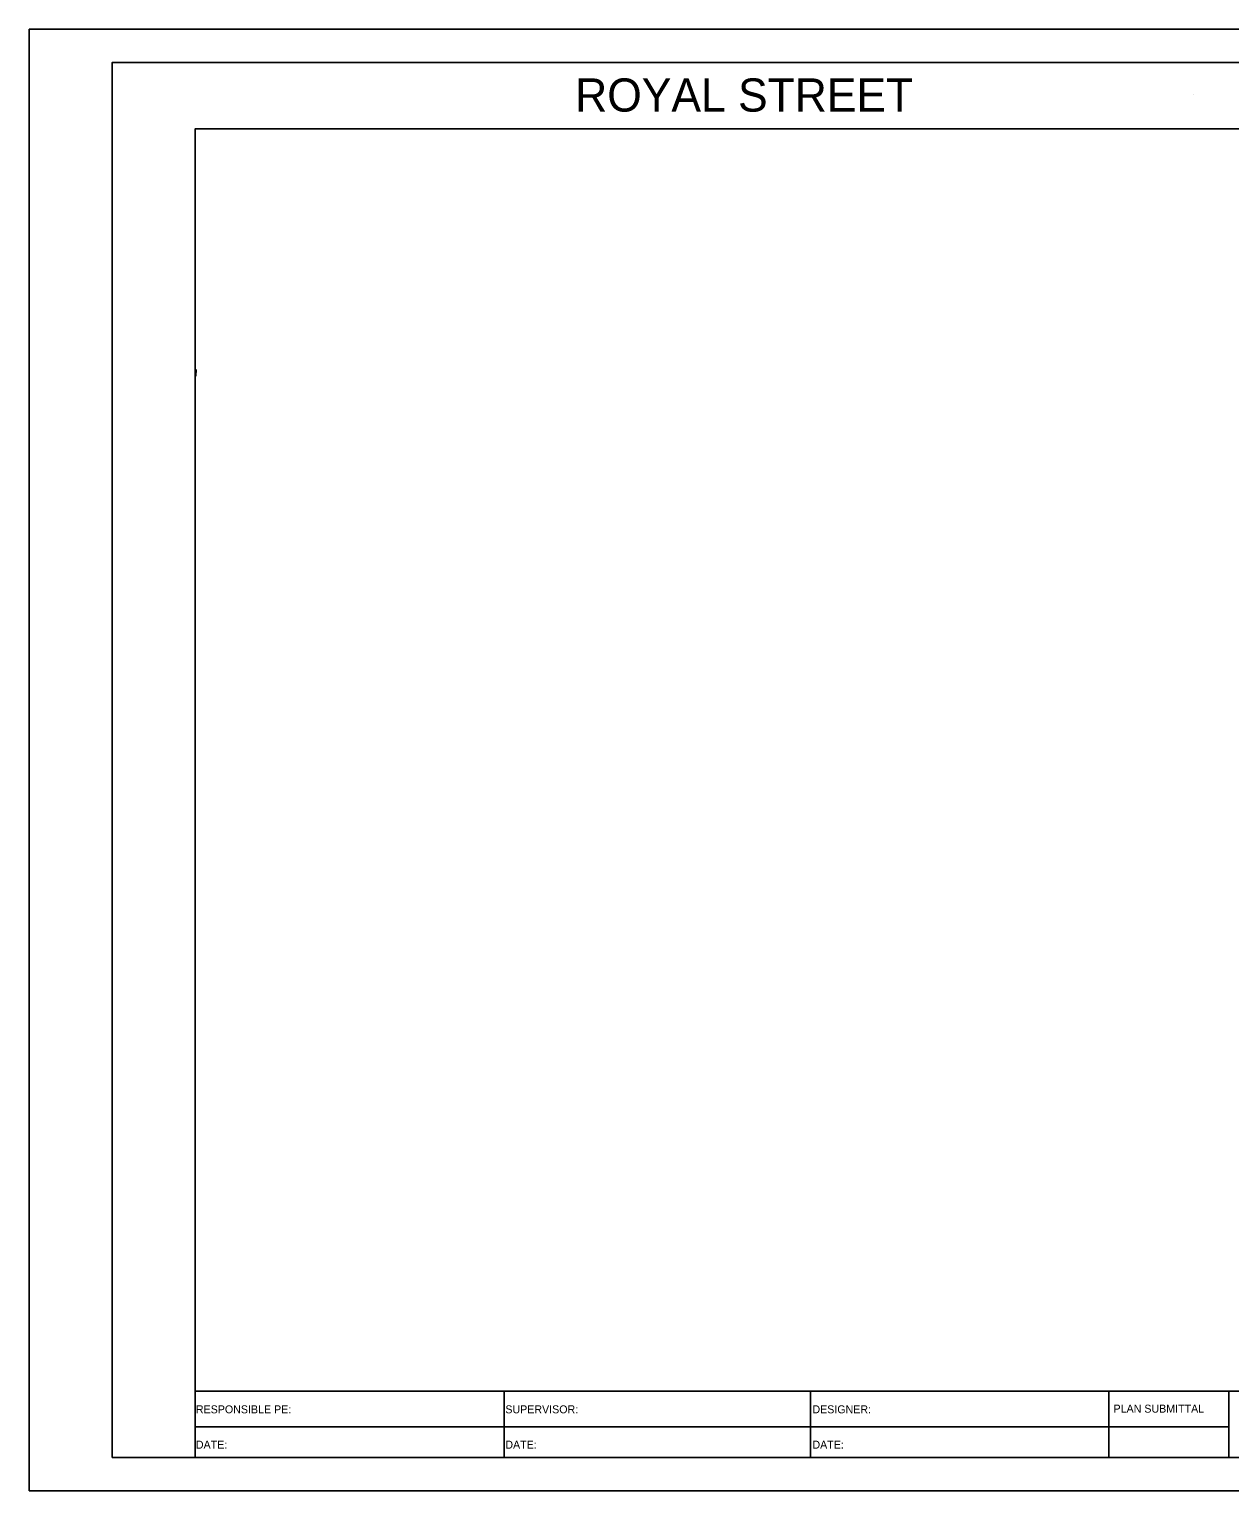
# Model space of a CAD drawing. Extents: x 1797478 to 1802456, y 246529 to 250952.
# Drawn here: x 1802116 to 1802296.8, y 250064.4 to 250284.4 of the extents above; entities that cross this region are included whole.
import ezdxf

# ---------------------------------------------------------------- set-up
doc = ezdxf.new("R2010")
doc.units = 0
for name, color, linetype in [('2', 7, 'Continuous'), ('ANNO-SHT', 7, 'Continuous'), ('ANNO-TXT', 7, 'Continuous'), ('AXIS', 7, 'Continuous'), ('DRAINAGE', 7, 'Continuous'), ('Level 1', 7, 'Continuous'), ('Level 62', 7, 'Continuous'), ('SHT-BDR', 7, 'Continuous'), ('SHT-BNDRY', 7, 'Continuous')]:
    doc.layers.add(name, color=color, linetype=linetype)

# ---------------------------------------------------------------- blocks, each defined once
blk = doc.blocks.new('SC47208')
at = {"layer": 'Level 1'}
blk.add_line((0, 0), (0, 0), dxfattribs=at)

msp = doc.modelspace()

# ---------------------------------------------------------------- linework, layer by layer
at = {"layer": '2'}
msp.add_lwpolyline([(1802141.12, 250233.21), (1802141.1, 250232.21)], dxfattribs=at)
msp.add_lwpolyline([(1802141.12, 250233.21), (1802141.1, 250232.21)], dxfattribs=at)
at = {"layer": 'AXIS'}
msp.add_line((1802141, 250189.42), (1802141, 250189.43), dxfattribs=at)
at = {"layer": 'Level 62'}
msp.add_lwpolyline([(1802116, 250064.42), (1802456, 250064.42), (1802456, 250284.42), (1802116, 250284.42)], close=True, dxfattribs=at)
at = {"layer": 'SHT-BDR'}
msp.add_lwpolyline([(1802141, 250079.43), (1802441, 250079.43), (1802441, 250269.43), (1802141, 250269.43)], close=True, dxfattribs=at)
at = {"layer": 'SHT-BNDRY'}
for p, q in [((1802141, 250069.42), (1802141, 250079.43)), ((1802187.52, 250079.43), (1802187.52, 250069.42)), ((1802233.67, 250069.42), (1802233.67, 250079.43)), ((1802278.59, 250069.42), (1802278.59, 250079.43)), ((1802296.63, 250069.42), (1802296.63, 250079.43)), ((1802141, 250074.03), (1802296.63, 250074.03))]:
    msp.add_line(p, q, dxfattribs=at)
msp.add_lwpolyline([(1802128.5, 250069.42), (1802451, 250069.42), (1802451, 250279.42), (1802128.5, 250279.42)], close=True, dxfattribs=at)

# ---------------------------------------------------------------- block references
at = {"layer": 'DRAINAGE', "xscale": 0.2, "yscale": 0.20000000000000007, "rotation": -116.41666666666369}
msp.add_blockref('SC47208', (1802291.32, 250274.62), dxfattribs=at)
msp.add_blockref('SC47208', (1802291.32, 250274.62), dxfattribs=at)

# ---------------------------------------------------------------- texts
at = {"layer": 'ANNO-SHT'}
msp.add_text('                     ROYAL STREET             ', height=4.9995, rotation=360, dxfattribs=at).set_placement((1802159.21, 250272.02))
at = {"layer": 'ANNO-TXT'}
for s, p in [('RESPONSIBLE PE:', (1802141.1, 250076.08)), ('SUPERVISOR:', (1802187.7, 250076.08)), ('DESIGNER:', (1802233.94, 250076.08)), ('PLAN SUBMITTAL', (1802279.28, 250076.18)), ('DATE:', (1802141.1, 250070.76)), ('DATE:', (1802187.7, 250070.76)), ('DATE:', (1802233.94, 250070.76))]:
    msp.add_text(s, height=1.2, rotation=360, dxfattribs=at).set_placement(p)

doc.saveas('drawing.dxf')
